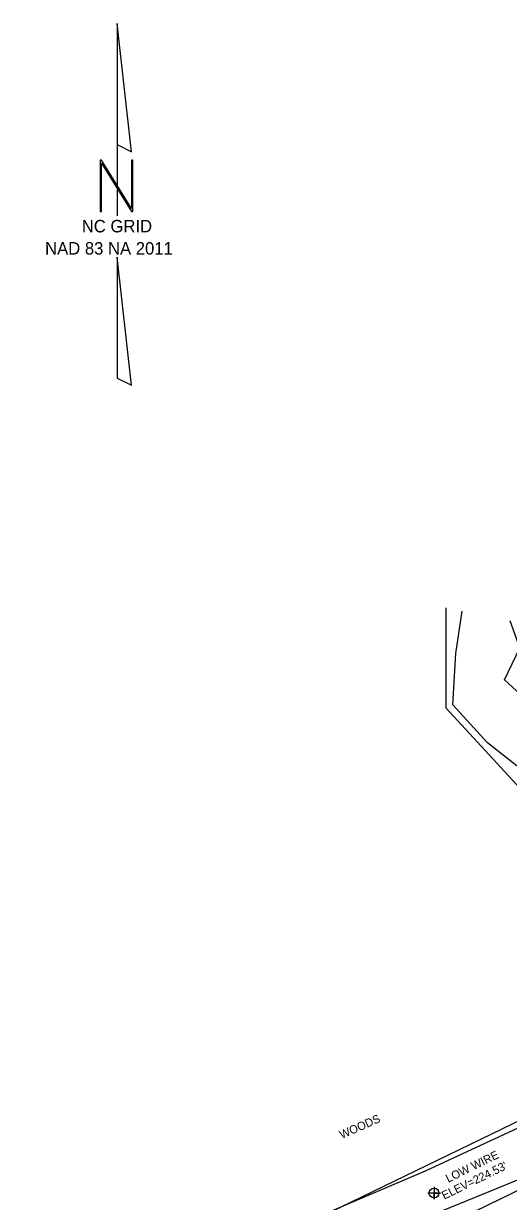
# Model space of a CAD drawing. Extents: x 2317197 to 2318671, y 941884 to 943470.
# Drawn here: x 2318004 to 2318238, y 942552 to 943119 of the extents above; entities that cross this region are included whole.
import ezdxf

# ---------------------------------------------------------------- set-up
doc = ezdxf.new("R2010")
doc.units = 0
for name, color, linetype in [('CTL North Arrow NAD 83 NA 2011 CELL', 7, 'Continuous'), ('Default Symbol CELL', 7, 'Continuous'), ('Default Symbol Text', 7, 'Continuous'), ('Exist Hydro Jurisdictional Stream or Body of Water', 7, 'Continuous'), ('Exist Right of Way Easement Line', 7, 'Continuous'), ('Exist Vegetation Woods Line', 7, 'Continuous'), ('Exist Vegetation Woods Line Text', 7, 'Continuous')]:
    doc.layers.add(name, color=color, linetype=linetype)

msp = doc.modelspace()

# ---------------------------------------------------------------- linework, layer by layer
at = {"layer": 'CTL North Arrow NAD 83 NA 2011 CELL'}
msp.add_line((2318049.12, 943031.8), (2318049.12, 943031.8), dxfattribs=at)
for points in [[(2318048.97, 943119.09), (2318048.97, 943060.76), (2318055.85, 943057.33)], [(2318040.75, 943028.54), (2318041.43, 943028.54), (2318041.43, 943051.86), (2318055.85, 943028.54), (2318056.53, 943028.54), (2318056.53, 943053.23), (2318055.85, 943053.23), (2318055.85, 943029.9), (2318041.43, 943053.23), (2318040.75, 943053.23)], [(2318048.97, 942948.25), (2318055.85, 942944.84), (2318048.97, 943006.58)]]:
    msp.add_lwpolyline(points, close=True, dxfattribs=at)
msp.add_lwpolyline([(2318048.97, 943060.76), (2318048.97, 943026.46)], dxfattribs=at)
at = {"layer": 'Default Symbol CELL'}
msp.add_lwpolyline([(2318201.69, 942558.57), (2318201.69, 942552.57), (2318201.69, 942555.57), (2318204.69, 942555.57), (2318198.69, 942555.57)], dxfattribs=at)
msp.add_circle((2318201.69, 942555.57), 2.34, dxfattribs=at)
at = {"layer": 'Exist Hydro Jurisdictional Stream or Body of Water'}
for points in [[(2318535.3, 942771.47), (2318515.83, 942752.18), (2318496, 942738.2), (2318475.44, 942726.82), (2318457.48, 942715.87), (2318430.01, 942696.42), (2318414.58, 942684.49), (2318393.33, 942675.63), (2318378.71, 942669.17), (2318355.7, 942675.78), (2318333.76, 942684.19), (2318309.82, 942696.76), (2318292.41, 942712.02), (2318274.96, 942724.1), (2318261.75, 942734.87), (2318247.01, 942757.06), (2318227.38, 942772.58), (2318210.69, 942790.86), (2318212.07, 942815.47), (2318215.15, 942836)], [(2318501.27, 942779.19), (2318500.65, 942776.96), (2318478.91, 942758.04), (2318462.02, 942748.9), (2318427.82, 942719.95), (2318417.95, 942713.05), (2318405.14, 942703.16), (2318388.37, 942699.42), (2318380.68, 942698.39), (2318365.37, 942700.99), (2318344.41, 942702.3), (2318330.15, 942722.49), (2318307.69, 942734.85), (2318295.39, 942745.8), (2318281.66, 942760.54), (2318235.65, 942802.84), (2318243.03, 942818.33), (2318238.27, 942831.28)]]:
    msp.add_lwpolyline(points, dxfattribs=at)
at = {"layer": 'Exist Right of Way Easement Line'}
for p, q in [((2317580.08, 942269.97), (2318408.71, 942670.8)), ((2317593.15, 942242.96), (2318435.75, 942650.55))]:
    msp.add_line(p, q, dxfattribs=at)
at = {"layer": 'Exist Vegetation Woods Line'}
for points in [[(2318207.34, 942837.53), (2318207.34, 942789.44), (2318256.63, 942735.95), (2318311.14, 942693.24), (2318377.34, 942667.16), (2318393.73, 942670.29), (2318398.49, 942658.49), (2318376.81, 942646.78), (2318327.72, 942621.04), (2318283.89, 942607.22), (2318242, 942586.89), (2318197.3, 942566.1), (2318149.43, 942545.66), (2318104.96, 942522.15), (2318066.57, 942501.46)], [(2317566.47, 942252.86), (2317585.52, 942245.38), (2317614.8, 942257.62), (2317655.31, 942278.17), (2317696.98, 942297.95), (2317735.39, 942318.15), (2317779.98, 942340.46), (2317814.58, 942353.56), (2317855.74, 942373.52), (2317898.59, 942394.26), (2317941.65, 942416.26), (2317988.39, 942435.8), (2318033.15, 942458.71), (2318078.29, 942479), (2318117.02, 942498.93), (2318158.1, 942521.54), (2318202.74, 942545.82), (2318250.98, 942565.6), (2318287.39, 942583.35), (2318333.94, 942598.89), (2318377.64, 942618.89), (2318423.51, 942637.15), (2318431.19, 942608.76), (2318442.13, 942565.53)]]:
    msp.add_lwpolyline(points, dxfattribs=at)

# ---------------------------------------------------------------- texts
at = {"layer": 'CTL North Arrow NAD 83 NA 2011 CELL'}
for s, p in [('NC GRID', (2318031.89, 943018.47)), ('NAD 83 NA 2011', (2318014.2, 943007.78))]:
    msp.add_text(s, height=6, dxfattribs=at).set_placement(p)
at = {"layer": 'Default Symbol Text'}
for s, p in [('LOW WIRE', (2318208.45, 942560.49)), ("ELEV=224.53' ", (2318206.54, 942552.32))]:
    msp.add_text(s, height=4, rotation=26.077, dxfattribs=at).set_placement(p)
at = {"layer": 'Exist Vegetation Woods Line Text'}
msp.add_text('WOODS', height=4, rotation=23.8142, dxfattribs=at).set_placement((2318157.15, 942581.58))

doc.saveas('drawing.dxf')
